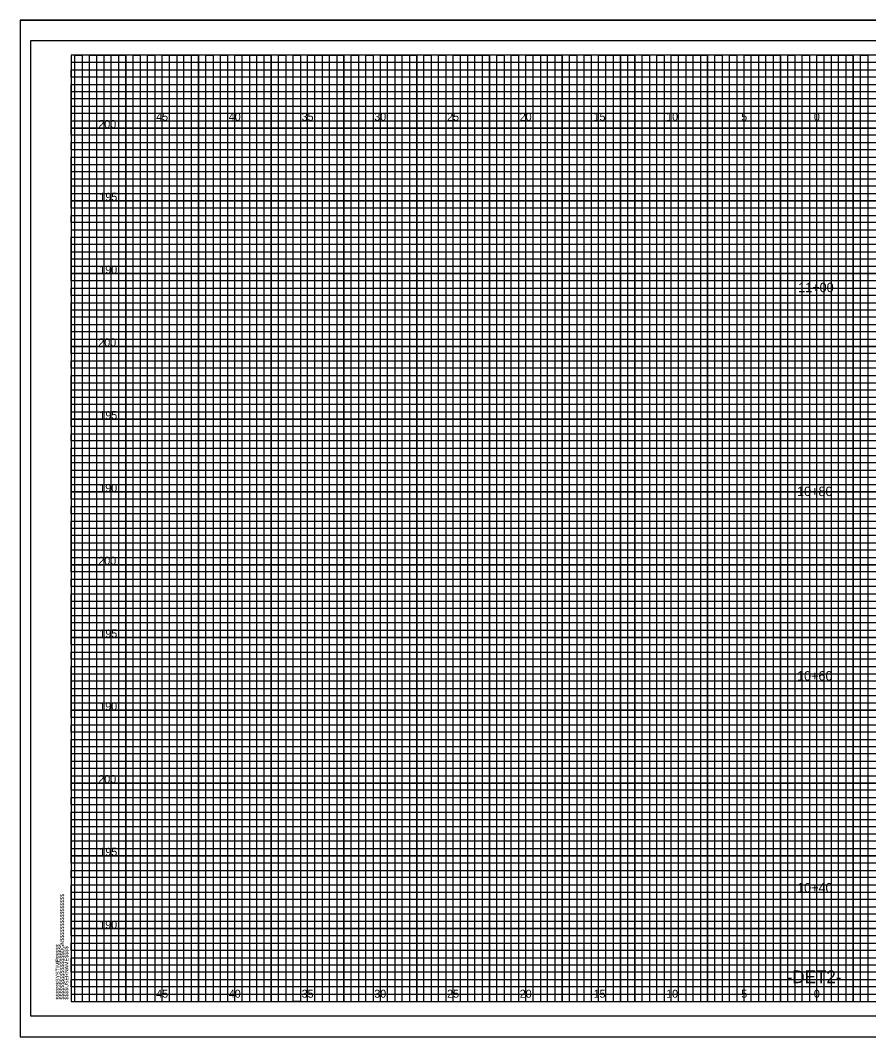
# Model space of a CAD drawing. Extents: x -4 to 103, y -2 to 209.
# Drawn here: x -3.5 to 54.8, y -2.4 to 67.4 of the extents above; entities that cross this region are included whole.
import ezdxf

# ---------------------------------------------------------------- set-up
doc = ezdxf.new("R2010")
doc.units = 0
for name, color, linetype in [('Exist XS Ground Line', 7, 'Continuous'), ('Old_Level_10', 7, 'Continuous'), ('Old_Level_3', 7, 'Continuous'), ('Old_Level_5', 7, 'Continuous'), ('Old_Level_8', 7, 'Continuous'), ('Prop XS Dump Level', 7, 'Continuous'), ('Prop XS Elevation Labels', 7, 'Continuous'), ('Prop XS EOT Tick Mark', 7, 'Continuous'), ('Prop XS Finish Grade', 7, 'Continuous'), ('Prop XS Hydro Elevations', 7, 'Continuous'), ('Prop XS Label Text', 7, 'Continuous')]:
    doc.layers.add(name, color=color, linetype=linetype)

msp = doc.modelspace()

# ---------------------------------------------------------------- linework, layer by layer
at = {"layer": 'Exist XS Ground Line'}
msp.add_lwpolyline([(103, 66), (-2.8, 66), (-2.8, -1), (103, -1)], close=True, dxfattribs=at)
at = {"layer": 'Old_Level_10'}
for p, q in [((1.25, 0), (1.25, 65)), ((3.75, 0), (3.75, 65)), ((6.25, 0), (6.25, 65)), ((8.75, 0), (8.75, 65)), ((11.25, 0), (11.25, 65)), ((13.75, 0), (13.75, 65)), ((16.25, 0), (16.25, 65)), ((18.75, 0), (18.75, 65)), ((21.25, 0), (21.25, 65)), ((23.75, 0), (23.75, 65)), ((26.25, 0), (26.25, 65)), ((28.75, 0), (28.75, 65)), ((31.25, 0), (31.25, 65)), ((33.75, 0), (33.75, 65)), ((36.25, 0), (36.25, 65)), ((38.75, 0), (38.75, 65)), ((41.25, 0), (41.25, 65)), ((43.75, 0), (43.75, 65)), ((46.25, 0), (46.25, 65)), ((48.75, 0), (48.75, 65)), ((51.25, 0), (51.25, 65)), ((53.75, 0), (53.75, 65)), ((0, 62.5), (74.25, 62.5)), ((0, 60), (102.5, 60)), ((0, 57.5), (102.5, 57.5)), ((0, 55), (102.5, 55)), ((0, 52.5), (102.5, 52.5)), ((0, 50), (102.5, 50)), ((0, 47.5), (102.5, 47.5)), ((0, 45), (102.5, 45)), ((0, 42.5), (102.5, 42.5)), ((0, 40), (102.5, 40)), ((0, 37.5), (102.5, 37.5)), ((0, 35), (102.5, 35)), ((0, 32.5), (102.5, 32.5)), ((0, 30), (102.5, 30)), ((0, 27.5), (102.5, 27.5)), ((0, 25), (102.5, 25)), ((0, 22.5), (102.5, 22.5)), ((0, 20), (102.5, 20)), ((0, 17.5), (102.5, 17.5)), ((0, 15), (102.5, 15)), ((0, 12.5), (102.5, 12.5)), ((0, 10), (102.5, 10)), ((0, 7.5), (102.5, 7.5)), ((0, 5), (102.5, 5)), ((0, 2.5), (102.5, 2.5))]:
    msp.add_line(p, q, dxfattribs=at)
at = {"layer": 'Old_Level_3'}
for p, q in [((-3.5, 67.4), (103.4, 67.4)), ((-3.5, 67.4), (-3.5, -2.425)), ((-3.5, -2.425), (103.4, -2.425))]:
    msp.add_line(p, q, dxfattribs=at)
at = {"layer": 'Old_Level_5'}
msp.add_lwpolyline([(103.4, 67.4), (-3.5, 67.4), (-3.5, -2.425), (103.4, -2.425)], close=True, dxfattribs=at)
at = {"layer": 'Old_Level_8'}
for points in [[(1.25, 0), (1.25, 65), (3.75, 65), (3.75, 0), (6.25, 0), (6.25, 65), (8.75, 65), (8.75, 0), (11.25, 0), (11.25, 65), (13.75, 65), (13.75, 0), (16.25, 0), (16.25, 65), (18.75, 65), (18.75, 0), (21.25, 0), (21.25, 65), (23.75, 65), (23.75, 0), (26.25, 0), (26.25, 65), (28.75, 65), (28.75, 0), (31.25, 0), (31.25, 65), (33.75, 65), (33.75, 0), (36.25, 0), (36.25, 65), (38.75, 65), (38.75, 0), (41.25, 0), (41.25, 65), (43.75, 65), (43.75, 0), (46.25, 0), (46.25, 65), (48.75, 65), (48.75, 0), (51.25, 0), (51.25, 65), (53.75, 65), (53.75, 0)], [(102.5, 60), (0, 60), (0, 62.5), (74.25, 62.5)], [(102.5, 55), (0, 55), (0, 57.5), (102.5, 57.5)], [(102.5, 50), (0, 50), (0, 52.5), (102.5, 52.5)], [(102.5, 45), (0, 45), (0, 47.5), (102.5, 47.5)], [(102.5, 40), (0, 40), (0, 42.5), (102.5, 42.5)], [(102.5, 35), (0, 35), (0, 37.5), (102.5, 37.5)], [(102.5, 30), (0, 30), (0, 32.5), (102.5, 32.5)], [(102.5, 25), (0, 25), (0, 27.5), (102.5, 27.5)], [(102.5, 20), (0, 20), (0, 22.5), (102.5, 22.5)], [(102.5, 15), (0, 15), (0, 17.5), (102.5, 17.5)], [(102.5, 10), (0, 10), (0, 12.5), (102.5, 12.5)], [(102.5, 5), (0, 5), (0, 7.5), (102.5, 7.5)], [(0, 2.5), (102.5, 2.5)]]:
    msp.add_lwpolyline(points, dxfattribs=at)
at = {"layer": 'Prop XS Dump Level'}
msp.add_lwpolyline([(102.5, 65), (0, 65), (0, 0), (102.5, 0)], close=True, dxfattribs=at)
at = {"layer": 'Prop XS Finish Grade'}
for points in [[(0.25, 0), (0.25, 65), (0.75, 65), (0.75, 0), (1.75, 0), (1.75, 65), (2.25, 65), (2.25, 0), (2.75, 0), (2.75, 65), (3.25, 65), (3.25, 0), (4.25, 0), (4.25, 65), (4.75, 65), (4.75, 0), (5.25, 0), (5.25, 65), (5.75, 65), (5.75, 0), (6.75, 0), (6.75, 65), (7.25, 65), (7.25, 0), (7.75, 0), (7.75, 65), (8.25, 65), (8.25, 0), (9.25, 0), (9.25, 65), (9.75, 65), (9.75, 0), (10.25, 0), (10.25, 65), (10.75, 65), (10.75, 0), (11.75, 0), (11.75, 65), (12.25, 65), (12.25, 0), (12.75, 0), (12.75, 65), (13.25, 65), (13.25, 0), (14.25, 0), (14.25, 65), (14.75, 65), (14.75, 0), (15.75, 0), (15.25, 0), (15.25, 65), (15.75, 65), (15.75, 0), (16.75, 0), (16.75, 65), (17.25, 65), (17.25, 0), (17.75, 0), (17.75, 65), (18.25, 65), (18.25, 0), (19.25, 0), (19.25, 65), (19.75, 65), (19.75, 0), (20.25, 0), (20.25, 65), (20.75, 65), (20.75, 0), (21.75, 0), (21.75, 65), (22.25, 65), (22.25, 0), (22.75, 0), (22.75, 65), (23.25, 65), (23.25, 0), (24.25, 0), (24.25, 65), (24.75, 65), (24.75, 0), (25.25, 0), (25.25, 65), (25.75, 65), (25.75, 0), (26.75, 0), (26.75, 65), (27.25, 65), (27.25, 0), (27.75, 0), (27.75, 65), (28.25, 65), (28.25, 0), (29.25, 0), (29.25, 65), (29.75, 65), (29.75, 0), (30.25, 0), (30.25, 65), (30.75, 65), (30.75, 0)], [(30.75, 0), (31.75, 0), (31.75, 65), (32.25, 65), (32.25, 0), (32.75, 0), (32.75, 65), (33.25, 65), (33.25, 0), (34.25, 0), (34.25, 65), (34.75, 65), (34.75, 0), (35.25, 0), (35.25, 65), (35.75, 65), (35.75, 0), (36.75, 0), (36.75, 65), (37.25, 65), (37.25, 0), (37.75, 0), (37.75, 65), (37.75, 0)], [(38.25, 65), (38.25, 0), (39.25, 0), (39.25, 65), (39.75, 65), (39.75, 0), (40.25, 0), (40.25, 65), (40.75, 65), (40.75, 0), (41.75, 0), (41.75, 65), (42.25, 65), (42.25, 0), (42.75, 0), (42.75, 65), (43.25, 65), (43.25, 0), (43.75, 0), (44.25, 0), (44.25, 65), (44.75, 65), (44.75, 0), (45.25, 0), (45.25, 65), (45.75, 65), (45.75, 0), (46.75, 0), (46.75, 65), (47.25, 65), (47.25, 0), (47.75, 0), (47.75, 65), (48.25, 65), (48.25, 0), (49.25, 0), (49.25, 65), (49.75, 65), (49.75, 0), (50.25, 0), (50.25, 65), (50.75, 65), (50.75, 0), (51.75, 0), (51.75, 65), (52.25, 65), (52.25, 0), (52.75, 0), (52.75, 65), (53.25, 65), (53.25, 0), (54.25, 0), (54.25, 65), (54.75, 65), (54.75, 0), (55.25, 0)], [(0, 62), (0, 63), (74.25, 63), (74.25, 63.5), (0, 63.5), (0, 64), (74.25, 64), (74.25, 64.5), (0, 64.5)], [(102.5, 62), (0, 62)], [(102.5, 61), (0, 61), (0, 61.5), (102.5, 61.5)], [(102.5, 59.5), (0, 59.5), (0, 60.5), (102.5, 60.5)], [(102.5, 58.5), (0, 58.5), (0, 59), (102.5, 59)], [(102.5, 57), (0, 57), (0, 58), (102.5, 58)], [(102.5, 56), (0, 56), (0, 56.5), (102.5, 56.5)], [(102.5, 54.5), (0, 54.5), (0, 55.5), (102.5, 55.5)], [(102.5, 53.5), (0, 53.5), (0, 54), (102.5, 54)], [(0, 53), (102.5, 53)], [(102.5, 52), (0, 52)], [(102.5, 51), (0, 51), (0, 51.5), (102.5, 51.5)], [(102.5, 49.5), (0, 49.5), (0, 50.5), (102.5, 50.5)], [(102.5, 48.5), (0, 48.5), (0, 49), (102.5, 49)], [(102.5, 47), (0, 47), (0, 48), (102.5, 48)], [(102.5, 46), (0, 46), (0, 46.5), (102.5, 46.5)], [(102.5, 44.5), (0, 44.5), (0, 45.5), (102.5, 45.5)], [(102.5, 43.5), (0, 43.5), (0, 44), (102.5, 44)], [(102.5, 42), (0, 42), (0, 43), (102.5, 43)], [(102.5, 41), (0, 41), (0, 41.5), (102.5, 41.5)], [(102.5, 39.5), (0, 39.5), (0, 40.5), (102.5, 40.5)], [(102.5, 38.5), (0, 38.5), (0, 39), (102.5, 39)], [(102.5, 37), (0, 37), (0, 38), (102.5, 38)], [(102.5, 36), (0, 36), (0, 36.5), (102.5, 36.5)], [(102.5, 34.5), (0, 34.5), (0, 35.5), (102.5, 35.5)], [(102.5, 33.5), (0, 33.5), (0, 34), (102.5, 34)], [(102.5, 32), (0, 32), (0, 33), (102.5, 33)], [(102.5, 31), (0, 31), (0, 31.5)], [(0, 31.5), (102.5, 31.5)], [(102.5, 29.5), (0, 29.5), (0, 30.5), (102.5, 30.5)], [(102.5, 28.5), (0, 28.5), (0, 29), (102.5, 29)], [(102.5, 27), (0, 27), (0, 28), (102.5, 28)], [(102.5, 26), (0, 26), (0, 26.5), (102.5, 26.5)], [(102.5, 24.5), (0, 24.5), (0, 25.5), (102.5, 25.5)], [(102.5, 23.5), (0, 23.5), (0, 24), (102.5, 24)], [(102.5, 22), (0, 22), (0, 23), (102.5, 23)], [(102.5, 21), (0, 21), (0, 21.5), (102.5, 21.5)], [(102.5, 19.5), (0, 19.5), (0, 20.5), (102.5, 20.5)], [(102.5, 18.5), (0, 18.5), (0, 19), (102.5, 19)], [(102.5, 17), (0, 17), (0, 18), (102.5, 18)], [(102.5, 16), (0, 16), (0, 16.5), (102.5, 16.5)], [(102.5, 14.5), (0, 14.5), (0, 15.5), (102.5, 15.5)], [(102.5, 13.5), (0, 13.5), (0, 14), (102.5, 14)], [(102.5, 12), (0, 12), (0, 13), (102.5, 13)], [(102.5, 11), (0, 11), (0, 11.5), (102.5, 11.5)], [(102.5, 9.5), (0, 9.5), (0, 10.5), (102.5, 10.5)], [(102.5, 8.5), (0, 8.5), (0, 9), (102.5, 9)], [(102.5, 7), (0, 7), (0, 8), (102.5, 8)], [(102.5, 6), (0, 6), (0, 6.5), (102.5, 6.5)], [(102.5, 4.5), (0, 4.5), (0, 5.5), (102.5, 5.5)], [(102.5, 3.5), (0, 3.5), (0, 4), (102.5, 4)], [(102.5, 2), (0, 2), (0, 3), (102.5, 3)], [(102.5, 1), (0, 1), (0, 1.5), (102.5, 1.5)], [(0, 0.5), (102.5, 0.5)]]:
    msp.add_lwpolyline(points, dxfattribs=at)

# ---------------------------------------------------------------- texts
at = {"layer": 'Old_Level_8'}
msp.add_text('040397', height=0.0025, rotation=90, dxfattribs=at).set_placement((-0.0007, 64.9864))
at = {"layer": 'Prop XS Dump Level'}
for s, p in [('$$$$$$$$$$$$$$$$DGN$$$$$$$$$$$$$$$$', (-0.5, 0.125)), ('$$$$$$SYSTIME$$$$$', (-0.7973, 0.1247)), ('$$$$USERNAME$$$$', (-0.2, 0.125))]:
    msp.add_text(s, height=0.2625, rotation=90, dxfattribs=at).set_placement(p)
at = {"layer": 'Prop XS Elevation Labels'}
for s, p in [('45', (5.8399, 60.5)), ('40', (10.8313, 60.5)), ('35', (15.8399, 60.5)), ('30', (20.8313, 60.5)), ('25', (25.8399, 60.5)), ('20', (30.8313, 60.5)), ('15', (35.9058, 60.5)), ('10', (40.8971, 60.5)), ('5', (46.0574, 60.5)), ('0', (51.0488, 60.5)), ('0', (51.0488, 60.5)), ('45', (5.8399, 0.25)), ('40', (10.8313, 0.25)), ('35', (15.8399, 0.25)), ('30', (20.8313, 0.25)), ('25', (25.8399, 0.25)), ('20', (30.8313, 0.25)), ('15', (35.9058, 0.25)), ('10', (40.8971, 0.25)), ('5', (46.0574, 0.25)), ('0', (51.0488, 0.25)), ('0', (51.0488, 0.25))]:
    msp.add_text(s, height=0.55, dxfattribs=at).set_placement(p)
at = {"layer": 'Prop XS EOT Tick Mark'}
msp.add_text('-DET2-', height=0.875, dxfattribs=at).set_placement((49.1786, 1.25))
at = {"layer": 'Prop XS Hydro Elevations'}
for s, p in [('11+00', (49.9712, 48.7233)), ('10+80', (49.8934, 34.7147)), ('10+60', (49.8934, 22.0372)), ('10+40', (49.8934, 7.4795))]:
    msp.add_text(s, height=0.65, dxfattribs=at).set_placement(p)
at = {"layer": 'Prop XS Label Text'}
for s, p in [('200', (1.8638, 60)), ('195', (1.9383, 55)), ('190', (1.9296, 50)), ('200', (1.8638, 45)), ('195', (1.9383, 40)), ('190', (1.9296, 35)), ('200', (1.8638, 30)), ('195', (1.9383, 25)), ('190', (1.9296, 20)), ('200', (1.8638, 15)), ('195', (1.9383, 10)), ('190', (1.9296, 5))]:
    msp.add_text(s, height=0.55, dxfattribs=at).set_placement(p)

doc.saveas('drawing.dxf')
